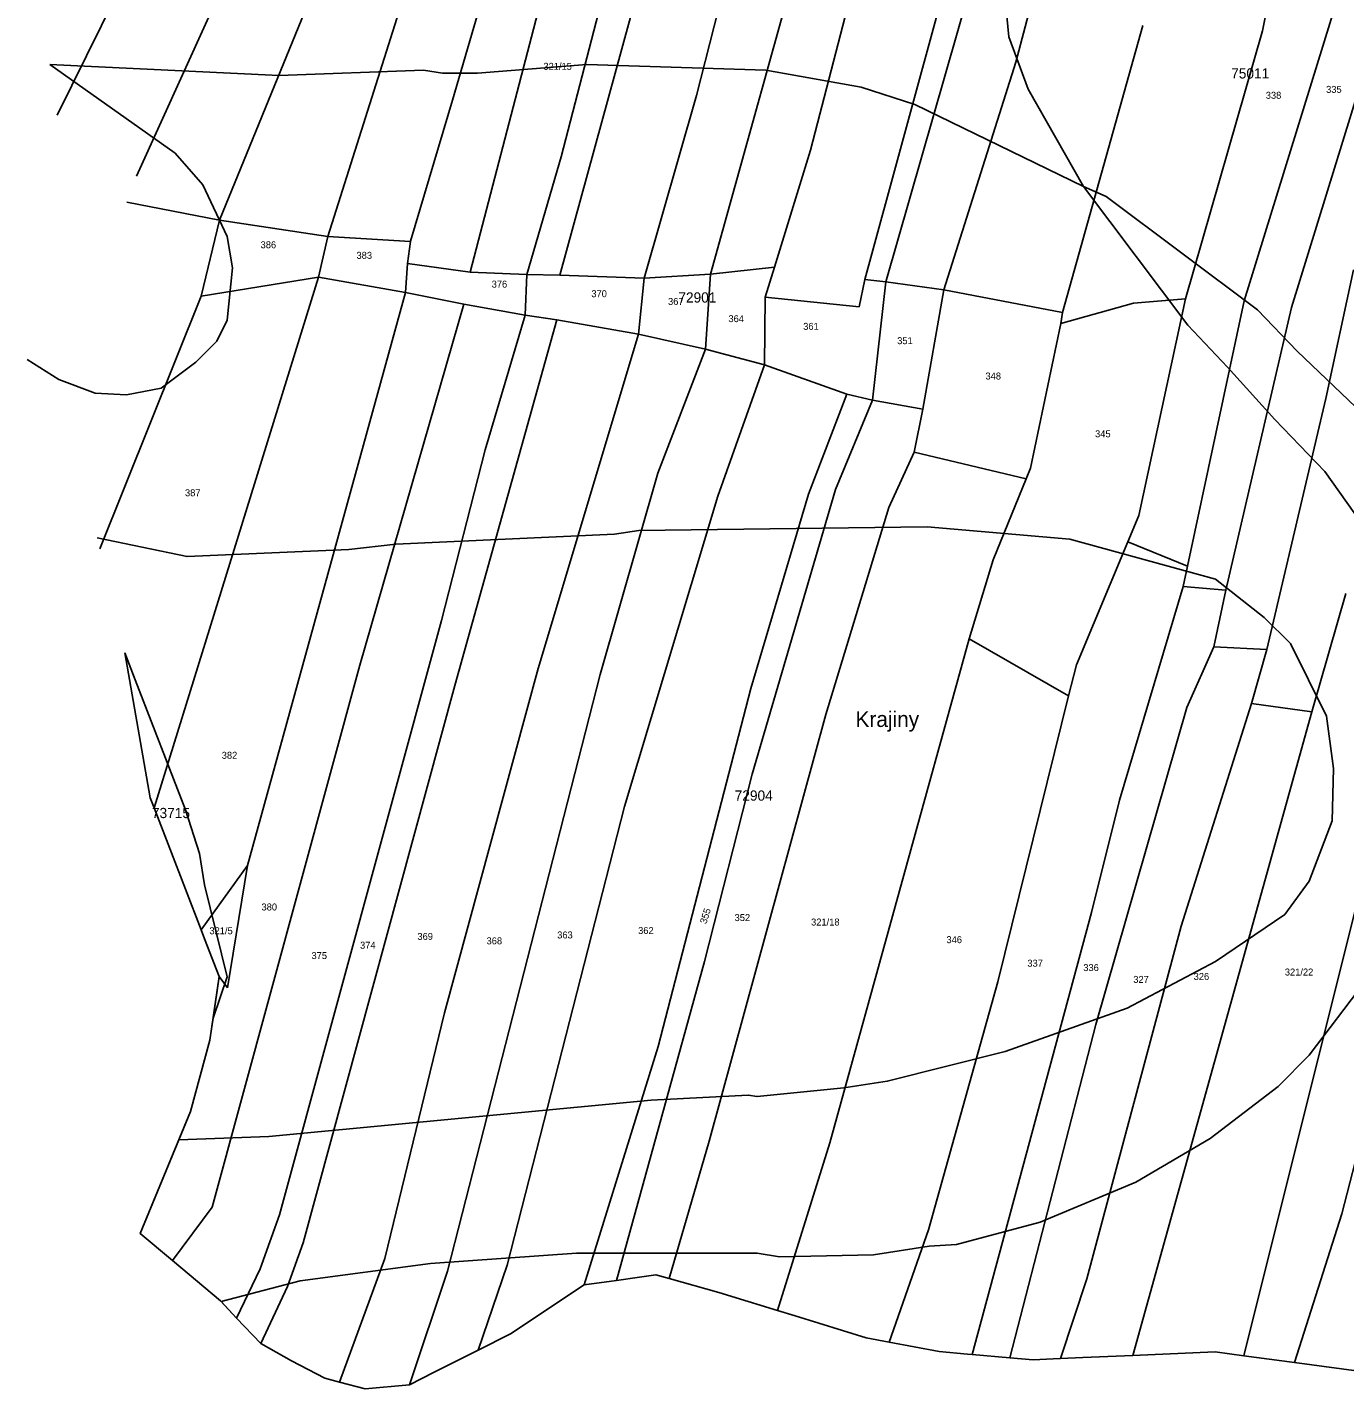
# Model space of a CAD drawing. Extents: x -743888 to -742027, y -1128394 to -1126768.
# Drawn here: x -743803.8 to -743482, y -1128009.6 to -1127677.1 of the extents above; entities that cross this region are included whole.
import ezdxf

# ---------------------------------------------------------------- set-up
doc = ezdxf.new("R2010")
doc.units = 0
for name, color, linetype in [('Vrstva 13', 7, 'Continuous'), ('Vrstva 15', 7, 'Continuous'), ('Vrstva 18', 7, 'Continuous'), ('Vrstva 52', 7, 'Continuous'), ('Vrstva 53', 7, 'Continuous'), ('Vrstva 6', 7, 'Continuous')]:
    doc.layers.add(name, color=color, linetype=linetype)

msp = doc.modelspace()

# ---------------------------------------------------------------- linework, layer by layer
at = {"layer": 'Vrstva 13'}
for points in [[(-743772.75, -1127867.77), (-743761.28, -1127897.56)], [(-743761.28, -1127897.56), (-743760.44, -1127899.72)], [(-743760.44, -1127899.72), (-743756.9, -1127908.92)], [(-743758.74, -1127921.72), (-743756.9, -1127908.92)], [(-743759.13, -1127924.43), (-743758.74, -1127921.72)], [(-743763.85, -1127941.89), (-743759.13, -1127924.43)], [(-743776.13, -1127971.68), (-743763.85, -1127941.89)], [(-743768.26, -1127978.29), (-743756.53, -1127988.15)], [(-743667.73, -1127984.22), (-743659.84, -1127983.12)], [(-743659.84, -1127983.12), (-743654.23, -1127982.34)], [(-743654.23, -1127982.34), (-743650.24, -1127981.78)], [(-743650.24, -1127981.78), (-743646.98, -1127982.69)], [(-743646.98, -1127982.69), (-743634.85, -1127986.07)], [(-743685.74, -1127996.16), (-743667.73, -1127984.22)], [(-743634.85, -1127986.07), (-743620.48, -1127990.48)], [(-743756.53, -1127988.15), (-743752.61, -1127992.31)], [(-743752.61, -1127992.31), (-743746.7, -1127998.56)], [(-743620.48, -1127990.48), (-743616.23, -1127991.79)], [(-743616.23, -1127991.79), (-743598.82, -1127997.13)], [(-743693.63, -1128000.15), (-743685.74, -1127996.16)], [(-743746.7, -1127998.56), (-743739.19, -1128002.73)], [(-743598.82, -1127997.13), (-743593.27, -1127998.19)], [(-743593.27, -1127998.19), (-743581.01, -1128000.52)], [(-743739.19, -1128002.73), (-743731.1, -1128007.03)], [(-743704.36, -1128005.57), (-743693.63, -1128000.15)], [(-743581.01, -1128000.52), (-743574.12, -1128001.12)], [(-743574.12, -1128001.12), (-743572.96, -1128001.22)], [(-743572.96, -1128001.22), (-743563.76, -1128002.02)], [(-743563.76, -1128002.02), (-743558.09, -1128002.51)], [(-743558.09, -1128002.51), (-743551.55, -1128002.22)], [(-743551.55, -1128002.22), (-743551.38, -1128002.22)], [(-743551.38, -1128002.22), (-743545.92, -1128001.98)], [(-743545.92, -1128001.98), (-743533.73, -1128001.44)], [(-743533.73, -1128001.44), (-743513.65, -1128000.56)], [(-743513.65, -1128000.56), (-743506.61, -1128001.51)], [(-743506.61, -1128001.51), (-743494.24, -1128003.18)], [(-743710.41, -1128008.62), (-743704.36, -1128005.57)], [(-743494.24, -1128003.18), (-743467.06, -1128006.86)], [(-743731.1, -1128007.03), (-743727.47, -1128007.97)], [(-743727.47, -1128007.97), (-743721.18, -1128009.59)], [(-743721.18, -1128009.59), (-743710.41, -1128008.62)]]:
    msp.add_lwpolyline(points, dxfattribs=at)
at = {"layer": 'Vrstva 52'}
for points in [[(-743545.75, -1127716), (-743559.31, -1127692.25), (-743564, -1127679.5), (-743565.69, -1127661.75)], [(-743798.19, -1127686.25), (-743767.63, -1127707.88), (-743760.88, -1127715.63), (-743754.88, -1127728.25), (-743753.63, -1127735.88), (-743754.88, -1127748.63), (-743757.44, -1127753.75), (-743762.56, -1127758.88), (-743771, -1127765.25), (-743779.5, -1127766.88), (-743787.13, -1127766.5), (-743796.06, -1127763.13), (-743803.75, -1127758.28)], [(-743798.19, -1127686.25), (-743742.19, -1127688.88), (-743706.94, -1127687.63), (-743702.31, -1127688.38), (-743693.81, -1127688.38), (-743667.06, -1127686.25), (-743623.38, -1127687.63), (-743600.06, -1127691.75), (-743586.94, -1127696), (-743545.75, -1127716)], [(-743545.75, -1127716), (-743540.25, -1127718.5), (-743503.31, -1127746.13), (-743493.56, -1127756.25), (-743477.44, -1127771.63), (-743470.69, -1127776.63), (-743449.44, -1127789.38), (-743433.31, -1127795.75), (-743410, -1127799.13), (-743369.25, -1127802.5)], [(-743545.75, -1127716), (-743520.31, -1127749.88), (-743510.56, -1127760.13), (-743499.06, -1127772.88), (-743486.81, -1127785.63), (-743477.88, -1127798.25)], [(-743786.67, -1127801.84), (-743764.69, -1127806.38), (-743725.19, -1127804.63), (-743713.75, -1127803.38), (-743660.31, -1127800.88), (-743654.38, -1127800), (-743583.94, -1127799.13), (-743549.13, -1127802.13), (-743513.5, -1127811.88), (-743501.63, -1127821.25), (-743495.25, -1127827.63), (-743486.38, -1127845.38), (-743484.69, -1127858.13), (-743485.06, -1127870.88), (-743490.63, -1127885.63), (-743496.56, -1127893.75), (-743513.5, -1127905.25), (-743535.13, -1127916.63), (-743564.88, -1127927.25), (-743593.69, -1127934.5), (-743604.31, -1127936.13), (-743625.5, -1127938.25), (-743627.63, -1127937.88), (-743651.38, -1127939.13), (-743744.75, -1127948), (-743766.71, -1127948.83)], [(-743758.37, -1127919.12), (-743754.88, -1127909), (-743760.44, -1127886.5), (-743761.69, -1127878.88), (-743765.06, -1127868.25), (-743777.38, -1127836.5), (-743779.89, -1127829.9)], [(-743779.89, -1127829.9), (-743773.7, -1127865.3), (-743772.75, -1127867.77), (-743761.28, -1127897.56), (-743760.44, -1127899.72), (-743756.9, -1127908.92), (-743758.37, -1127919.12)], [(-743477.06, -1127910.25), (-743490.63, -1127928.13), (-743498.25, -1127935.75), (-743514.81, -1127948.5), (-743533, -1127959.13), (-743556.38, -1127968.88), (-743576.75, -1127974.38), (-743583.5, -1127974.75), (-743597.06, -1127976.88), (-743620, -1127977.38), (-743625.5, -1127976.5), (-743669.63, -1127976.5), (-743705.25, -1127979), (-743737.06, -1127983.25), (-743756.37, -1127988.32)], [(-743766.71, -1127948.83), (-743763.85, -1127941.89), (-743759.13, -1127924.43), (-743758.74, -1127921.72), (-743758.37, -1127919.12)], [(-743756.37, -1127988.32), (-743756.53, -1127988.15), (-743768.26, -1127978.29), (-743776.13, -1127971.68), (-743766.71, -1127948.83)], [(-743756.37, -1127988.32), (-743752.61, -1127992.31), (-743746.7, -1127998.56), (-743739.19, -1128002.73), (-743731.1, -1128007.03), (-743727.47, -1128007.97), (-743721.18, -1128009.59), (-743710.41, -1128008.62), (-743704.36, -1128005.57), (-743693.63, -1128000.15), (-743685.74, -1127996.16), (-743667.73, -1127984.22), (-743659.84, -1127983.12), (-743654.23, -1127982.34), (-743650.24, -1127981.78), (-743646.98, -1127982.69), (-743634.85, -1127986.07), (-743620.48, -1127990.48), (-743616.23, -1127991.79), (-743598.82, -1127997.13), (-743593.27, -1127998.19), (-743581.01, -1128000.52), (-743574.12, -1128001.12), (-743572.96, -1128001.22), (-743563.76, -1128002.02), (-743558.09, -1128002.51), (-743551.55, -1128002.22), (-743551.38, -1128002.22), (-743545.92, -1128001.98), (-743533.73, -1128001.44), (-743513.65, -1128000.56), (-743506.61, -1128001.51), (-743494.24, -1128003.18), (-743467.06, -1128006.86)]]:
    msp.add_lwpolyline(points, dxfattribs=at)
at = {"layer": 'Vrstva 6'}
for points in [[(-743640.25, -1127693.79), (-743606.94, -1127562.76)], [(-743777.04, -1127713.53), (-743714.07, -1127574.65)], [(-743673.31, -1127708.75), (-743643.68, -1127594.43)], [(-743612.44, -1127707.12), (-743584.91, -1127601.01)], [(-743695.53, -1127736.94), (-743664.09, -1127615.99)], [(-743796.4, -1127698.58), (-743756.85, -1127618.5)], [(-743562.33, -1127685.66), (-743545.56, -1127622.11)], [(-743502.02, -1127678), (-743491.75, -1127625.57)], [(-743599.16, -1127738.75), (-743570.37, -1127633.12)], [(-743699.9, -1127694.98), (-743682.11, -1127634.16)], [(-743756.8, -1127724.26), (-743724.77, -1127645.91)], [(-743730.37, -1127728.24), (-743704.24, -1127645.83)], [(-743636.86, -1127737.44), (-743612.33, -1127649.25)], [(-743673.66, -1127737.68), (-743649.9, -1127650.85)], [(-743506.51, -1127743.94), (-743482.22, -1127665.09)], [(-743494.95, -1127745.55), (-743469.86, -1127664.22)], [(-743594.04, -1127739.28), (-743573.61, -1127667.99)], [(-743550.89, -1127746.78), (-743531.28, -1127676.73)], [(-743520.82, -1127743.45), (-743502.02, -1127678)], [(-743579.85, -1127741.23), (-743562.33, -1127685.66)], [(-743653.09, -1127738.43), (-743640.25, -1127693.79)], [(-743710.12, -1127729.39), (-743699.9, -1127694.98)], [(-743621.23, -1127735.75), (-743612.44, -1127707.12)], [(-743681.73, -1127737.55), (-743673.31, -1127708.75)], [(-743779.45, -1127719.83), (-743756.8, -1127724.26)], [(-743761.26, -1127742.79), (-743756.8, -1127724.26)], [(-743756.8, -1127724.26), (-743730.37, -1127728.24)], [(-743732.64, -1127738.2), (-743730.37, -1127728.24)], [(-743730.37, -1127728.24), (-743710.14, -1127729.48)], [(-743710.85, -1127734.84), (-743710.14, -1127729.48)], [(-743710.14, -1127729.48), (-743710.12, -1127729.39)], [(-743711.36, -1127741.87), (-743710.85, -1127734.84)], [(-743710.85, -1127734.84), (-743695.53, -1127736.94)], [(-743695.53, -1127736.94), (-743681.73, -1127737.55)], [(-743636.86, -1127737.44), (-743621.23, -1127735.75)], [(-743623.51, -1127743.05), (-743621.23, -1127735.75)], [(-743486.56, -1127767.82), (-743479.83, -1127736.34)], [(-743772.75, -1127867.77), (-743732.64, -1127738.2)], [(-743761.26, -1127742.79), (-743732.64, -1127738.2)], [(-743732.64, -1127738.2), (-743711.36, -1127741.87)], [(-743682.17, -1127747.48), (-743681.73, -1127737.55)], [(-743681.73, -1127737.55), (-743673.66, -1127737.68)], [(-743673.66, -1127737.68), (-743653.09, -1127738.43)], [(-743654.42, -1127752.06), (-743653.09, -1127738.43)], [(-743653.09, -1127738.43), (-743636.86, -1127737.44)], [(-743638.13, -1127755.73), (-743636.86, -1127737.44)], [(-743600.59, -1127745.39), (-743599.16, -1127738.75)], [(-743599.16, -1127738.75), (-743594.04, -1127739.28)], [(-743597.33, -1127768.16), (-743594.04, -1127739.28)], [(-743594.04, -1127739.28), (-743579.85, -1127741.23)], [(-743786, -1127804.52), (-743761.26, -1127742.79)], [(-743749.96, -1127881.78), (-743711.36, -1127741.87)], [(-743711.36, -1127741.87), (-743697.14, -1127744.72)], [(-743623.67, -1127759.6), (-743623.51, -1127743.05)], [(-743623.51, -1127743.05), (-743600.59, -1127745.39)], [(-743585.04, -1127770.39), (-743579.85, -1127741.23)], [(-743579.85, -1127741.23), (-743550.89, -1127746.78)], [(-743533.58, -1127744.49), (-743520.82, -1127743.45)], [(-743532.26, -1127796.34), (-743520.82, -1127743.45)], [(-743722.54, -1127832.92), (-743697.14, -1127744.72)], [(-743697.14, -1127744.72), (-743682.17, -1127747.48)], [(-743551.29, -1127749.44), (-743533.58, -1127744.49)], [(-743551.29, -1127749.44), (-743550.89, -1127746.78)], [(-743520.33, -1127808.71), (-743506.51, -1127743.94)], [(-743511, -1127814.57), (-743494.95, -1127745.55)], [(-743699.34, -1127837.9), (-743674.43, -1127748.6)], [(-743691.92, -1127780.31), (-743682.17, -1127747.48)], [(-743682.17, -1127747.48), (-743674.43, -1127748.6)], [(-743674.43, -1127748.6), (-743654.42, -1127752.06)], [(-743558.72, -1127784.83), (-743551.29, -1127749.44)], [(-743678.95, -1127833.74), (-743654.42, -1127752.06)], [(-743654.42, -1127752.06), (-743638.13, -1127755.73)], [(-743649.76, -1127786.02), (-743638.13, -1127755.73)], [(-743638.13, -1127755.73), (-743623.67, -1127759.6)], [(-743635.09, -1127791.61), (-743623.67, -1127759.6)], [(-743623.67, -1127759.6), (-743603.54, -1127766.74)], [(-743612.96, -1127791.11), (-743603.54, -1127766.74)], [(-743603.54, -1127766.74), (-743597.33, -1127768.16)], [(-743606.36, -1127789.97), (-743597.33, -1127768.16)], [(-743597.33, -1127768.16), (-743585.04, -1127770.39)], [(-743587.1, -1127780.87), (-743585.04, -1127770.39)], [(-743500.98, -1127829.09), (-743486.56, -1127767.82)], [(-743702.59, -1127822), (-743691.92, -1127780.31)], [(-743593.35, -1127794.42), (-743587.1, -1127780.87)], [(-743587.1, -1127780.87), (-743559.77, -1127787.4)], [(-743663.84, -1127835.21), (-743649.76, -1127786.02)], [(-743559.77, -1127787.4), (-743558.72, -1127784.83)], [(-743626.72, -1127859.49), (-743606.36, -1127789.97)], [(-743567.83, -1127807.19), (-743559.77, -1127787.4)], [(-743657.85, -1127867.39), (-743635.09, -1127791.61)], [(-743627.05, -1127838.6), (-743612.96, -1127791.11)], [(-743608.73, -1127844.98), (-743593.35, -1127794.42)], [(-743534.94, -1127802.78), (-743532.26, -1127796.34)], [(-743547.45, -1127832.8), (-743534.94, -1127802.78)], [(-743534.94, -1127802.78), (-743520.33, -1127808.71)], [(-743573.69, -1127826.51), (-743567.83, -1127807.19)], [(-743521.42, -1127813.7), (-743520.33, -1127808.71)], [(-743536.99, -1127865.85), (-743521.42, -1127813.7)], [(-743521.42, -1127813.7), (-743511, -1127814.57)], [(-743513.93, -1127828.42), (-743511, -1127814.57)], [(-743490.01, -1127844.27), (-743481.69, -1127815.4)], [(-743742.13, -1127967.1), (-743702.59, -1127822)], [(-743607.74, -1127949.5), (-743573.69, -1127826.51)], [(-743573.69, -1127826.51), (-743549.4, -1127840.4)], [(-743520.57, -1127843.27), (-743513.93, -1127828.42)], [(-743513.93, -1127828.42), (-743500.98, -1127829.09)], [(-743504.76, -1127842.24), (-743500.98, -1127829.09)], [(-743758.56, -1127965.24), (-743722.54, -1127832.92)], [(-743549.4, -1127840.4), (-743547.45, -1127832.8)], [(-743701.86, -1127917.81), (-743678.95, -1127833.74)], [(-743701.08, -1127980.88), (-743663.84, -1127835.21)], [(-743736.36, -1127973.94), (-743699.34, -1127837.9)], [(-743649.69, -1127926.04), (-743627.05, -1127838.6)], [(-743566.66, -1127910.22), (-743549.4, -1127840.4)], [(-743542.77, -1127920.67), (-743520.57, -1127843.27)], [(-743521.89, -1127896.66), (-743504.76, -1127842.24)], [(-743504.76, -1127842.24), (-743490.01, -1127844.27)], [(-743637.18, -1127949.14), (-743608.73, -1127844.98)], [(-743533.73, -1128001.44), (-743490.01, -1127844.27)], [(-743638.35, -1127905.26), (-743626.72, -1127859.49)], [(-743543.84, -1127893.3), (-743536.99, -1127865.85)], [(-743686.5, -1127979.4), (-743657.85, -1127867.39)], [(-743761.28, -1127897.56), (-743749.96, -1127881.78)], [(-743754.87, -1127911.67), (-743749.96, -1127881.78)], [(-743506.61, -1128001.51), (-743476.79, -1127882.29)], [(-743572.96, -1128001.22), (-743543.84, -1127893.3)], [(-743544.94, -1127982.71), (-743521.89, -1127896.66)], [(-743659.84, -1127983.12), (-743638.35, -1127905.26)], [(-743756.9, -1127908.92), (-743754.87, -1127911.67)], [(-743583.63, -1127970.8), (-743566.66, -1127910.22)], [(-743482.7, -1127966.88), (-743469.54, -1127916.07)], [(-743716.39, -1127977.76), (-743701.86, -1127917.81)], [(-743563.76, -1128002.02), (-743542.77, -1127920.67)], [(-743667.73, -1127984.22), (-743649.69, -1127926.04)], [(-743646.98, -1127982.69), (-743637.18, -1127949.14)], [(-743620.48, -1127990.48), (-743607.74, -1127949.5)], [(-743768.26, -1127978.29), (-743758.56, -1127965.24)], [(-743746.82, -1127980.32), (-743742.13, -1127967.1)], [(-743494.24, -1128003.18), (-743482.7, -1127966.88)], [(-743593.27, -1127998.19), (-743583.63, -1127970.8)], [(-743740.21, -1127984.65), (-743736.36, -1127973.94)], [(-743727.47, -1128007.97), (-743716.39, -1127977.76)], [(-743693.63, -1128000.15), (-743686.5, -1127979.4)], [(-743752.61, -1127992.31), (-743746.82, -1127980.32)], [(-743710.41, -1128008.62), (-743701.08, -1127980.88)], [(-743551.38, -1128002.22), (-743544.94, -1127982.71)], [(-743746.7, -1127998.56), (-743740.21, -1127984.65)]]:
    msp.add_lwpolyline(points, dxfattribs=at)

# ---------------------------------------------------------------- texts
at = {"layer": 'Vrstva 15'}
msp.add_text('Krajiny', height=3.8, dxfattribs=at).set_placement((-743601.45, -1127847.99))
at = {"layer": 'Vrstva 18'}
for s, p in [('321/15', (-743677.68, -1127687.53)), ('338', (-743501.25, -1127694.6)), ('335', (-743486.51, -1127693.16)), ('386', (-743746.75, -1127731.1)), ('383', (-743723.33, -1127733.68)), ('376', (-743690.32, -1127740.71)), ('370', (-743665.97, -1127743.05)), ('367', (-743647.24, -1127744.93)), ('364', (-743632.49, -1127749.14)), ('361', (-743614.23, -1127751.02)), ('351', (-743591.27, -1127754.52)), ('348', (-743569.71, -1127763.15)), ('345', (-743542.94, -1127777.26)), ('387', (-743765.22, -1127791.66)), ('382', (-743756.24, -1127855.76)), ('380', (-743746.53, -1127892.8)), ('352', (-743630.98, -1127895.39)), ('321/18', (-743612.3, -1127896.47)), ('321/5', (-743759.25, -1127898.6)), ('369', (-743708.45, -1127899.99)), ('368', (-743691.56, -1127901.07)), ('363', (-743674.31, -1127899.63)), ('362', (-743654.55, -1127898.55)), ('346', (-743579.24, -1127900.78)), ('375', (-743734.32, -1127904.66)), ('374', (-743722.46, -1127902.14)), ('337', (-743559.48, -1127906.53)), ('336', (-743545.82, -1127907.6)), ('327', (-743533.61, -1127910.48)), ('326', (-743518.87, -1127909.76)), ('321/22', (-743496.6, -1127908.68))]:
    msp.add_text(s, height=1.7, dxfattribs=at).set_placement(p)
msp.add_text('355', height=1.7, rotation=72.3514, dxfattribs=at).set_placement((-743637.89, -1127896.2))
at = {"layer": 'Vrstva 53'}
for s, p in [('75011', (-743509.7, -1127689.65)), ('72901', (-743644.72, -1127744.37)), ('72904', (-743630.96, -1127865.99)), ('73715', (-743773.29, -1127870.25))]:
    msp.add_text(s, height=2.5, dxfattribs=at).set_placement(p)

doc.saveas('drawing.dxf')
